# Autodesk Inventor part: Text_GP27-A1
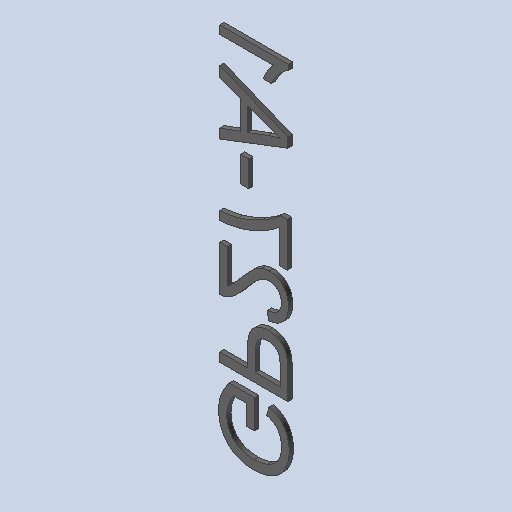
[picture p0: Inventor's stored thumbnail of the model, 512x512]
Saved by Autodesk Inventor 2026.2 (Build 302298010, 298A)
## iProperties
Created: 2026-10
Part Number: Text_GP27-A1
Material: Générique
Document SubType Name: Modeling
Designer: mel
Density: 1 g/cm^3
Appearance: Par défaut
Author: mel
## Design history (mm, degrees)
feature "Base1"
feature "Base2"
feature "Base3"
feature "Base4"
feature "Base5"
feature "Base6"
feature "Base7"
node "Solide1"
node "Solide2"
node "Solide3"
node "Solide4"
node "Solide5"
node "Solide6"
node "Solide7"
